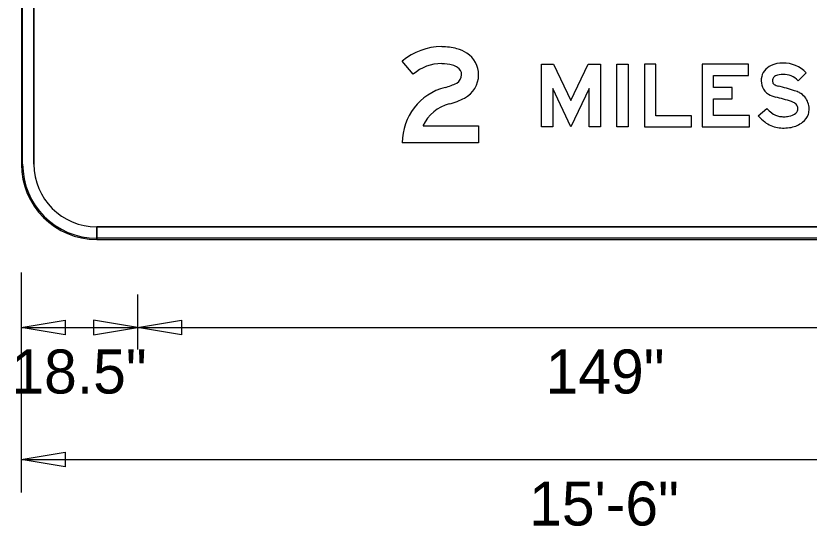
# Model space of a CAD drawing. Extents: x 2149961 to 2150220, y 145114 to 145240.
# Drawn here: x 2149983.36 to 2149993.88, y 145212.96 to 145219.73 of the extents above; entities that cross this region are included whole.
import ezdxf

# ---------------------------------------------------------------- set-up
doc = ezdxf.new("R2010")
doc.units = 0
for name, color, linetype in [('GSBWFILL', 7, 'Continuous'), ('GSCOLORFILL', 7, 'Continuous'), ('GSDIMS', 7, 'Continuous'), ('GSOUTLINE', 7, 'Continuous')]:
    doc.layers.add(name, color=color, linetype=linetype)

msp = doc.modelspace()

# ---------------------------------------------------------------- linework, layer by layer
at = {"layer": 'GSBWFILL'}
for p, q in [((2149983.43, 145232.262), (2149983.43, 145217.762)), ((2149983.596, 145217.762), (2149983.596, 145232.262)), ((2149984.43, 145216.762), (2149984.43, 145216.929)), ((2149997.93, 145216.929), (2149984.431, 145216.929)), ((2149984.431, 145216.929), (2149984.431, 145216.762)), ((2149984.431, 145216.762), (2149997.93, 145216.762))]:
    msp.add_line(p, q, dxfattribs=at)
for points in [[(2149988.628, 145218.954), (2149988.483, 145219.125)], [(2149993.84, 145218.972), (2149993.733, 145218.867)], [(2149993.203, 145218.401), (2149993.317, 145218.499)], [(2149988.758, 145218.27), (2149989.495, 145218.27), (2149989.495, 145218.045), (2149988.483, 145218.045)]]:
    msp.add_lwpolyline(points, dxfattribs=at)
for points in [[(2149990.72, 145218.603), (2149990.95, 145219.087), (2149991.112, 145219.087), (2149991.112, 145218.254), (2149990.962, 145218.254), (2149990.962, 145218.762), (2149990.72, 145218.254), (2149990.478, 145218.762), (2149990.478, 145218.254), (2149990.328, 145218.254), (2149990.328, 145219.087), (2149990.49, 145219.087)], [(2149991.328, 145218.254), (2149991.328, 145219.087), (2149991.478, 145219.087), (2149991.478, 145218.254)], [(2149992.32, 145218.254), (2149992.32, 145218.399), (2149991.845, 145218.399), (2149991.845, 145219.087), (2149991.695, 145219.087), (2149991.695, 145218.254)], [(2149993.087, 145218.404), (2149992.612, 145218.404), (2149992.612, 145218.628), (2149992.858, 145218.628), (2149992.858, 145218.778), (2149992.612, 145218.778), (2149992.612, 145218.937), (2149993.074, 145218.937), (2149993.074, 145219.087), (2149992.462, 145219.087), (2149992.462, 145218.254), (2149993.087, 145218.254)]]:
    msp.add_lwpolyline(points, close=True, dxfattribs=at)
for centre, radius, start, end in [((2149993.532, 145218.703), 0.398, 90, 113.3248), ((2149993.532, 145218.67), 0.431, 44.4342, 90), ((2149993.461, 145218.869), 0.218, 113.3248, 174.1421), ((2149993.481, 145218.867), 0.238, 174.1421, 201.2247), ((2149993.461, 145218.869), 0.0679, 113.3248, 174.1421), ((2149993.481, 145218.867), 0.0882, 174.1421, 201.2247), ((2149993.532, 145218.703), 0.248, 90, 113.3248), ((2149993.532, 145218.67), 0.281, 44.4342, 90), ((2149993.433, 145218.848), 0.186, 201.2247, 240.1812), ((2149993.433, 145218.848), 0.0363, 201.2247, 240.1812), ((2149993.519, 145218.998), 0.209, 240.1812, 256.1067), ((2149992.497, 145214.868), 4.045, 72.8961, 76.1067), ((2149993.519, 145218.998), 0.359, 240.1812, 256.1067), ((2149993.569, 145218.352), 0.4, 63.0108, 72.8961), ((2149993.65, 145218.51), 0.222, 39.5561, 63.0108), ((2149992.497, 145214.868), 3.895, 72.8961, 76.1067), ((2149993.569, 145218.352), 0.25, 63.0108, 72.8961), ((2149993.65, 145218.51), 0.0724, 39.5561, 63.0108), ((2149993.629, 145218.493), 0.0993, 0, 39.5561), ((2149993.629, 145218.493), 0.249, 0, 39.5561), ((2149993.643, 145218.781), 0.43, 220.8202, 232.6492), ((2149993.671, 145218.483), 0.0563, 306.0677, 343.4972), ((2149993.635, 145218.493), 0.0932, 343.4972, 0), ((2149993.635, 145218.493), 0.243, 343.4972, 0), ((2149993.643, 145218.781), 0.58, 220.8202, 232.6492), ((2149993.522, 145218.622), 0.231, 232.6492, 260.7349), ((2149993.547, 145218.777), 0.388, 260.7349, 270), ((2149993.547, 145218.695), 0.306, 270, 281.6446), ((2149993.56, 145218.635), 0.245, 281.6446, 306.0677), ((2149993.671, 145218.483), 0.206, 306.0677, 343.4972), ((2149993.522, 145218.622), 0.381, 232.6492, 260.7349), ((2149993.547, 145218.777), 0.538, 260.7349, 270), ((2149993.547, 145218.695), 0.456, 270, 281.6446), ((2149993.56, 145218.635), 0.395, 281.6446, 306.0677), ((2149984.43, 145217.762), 1, 180, 270), ((2149984.43, 145217.762), 0.833, 180, 270)]:
    msp.add_arc(centre, radius, start, end, dxfattribs=at)
for centre, major_axis, start_param, end_param in [((2149989.005, 145218.511), (0, 0.807), 0, 0.70376), ((2149989.005, 145218.527), (0, 0.79), 6.02311, 6.283185), ((2149989.09, 145218.847), (0, 0.458), 5.706931, 6.02311), ((2149989.153, 145218.945), (0, 0.342), 4.712389, 5.706931), ((2149989.005, 145218.511), (0, 0.582), 0, 0.70376), ((2149989.005, 145218.527), (0, 0.565), 6.02311, 6.283185), ((2149989.09, 145218.847), (0, 0.233), 5.706931, 6.02311), ((2149989.153, 145218.945), (0, 0.117), 4.712389, 5.706931), ((2149989.146, 145218.945), (0, 0.124), 3.626327, 4.712389), ((2149989.146, 145218.945), (0, 0.349), 3.626327, 4.712389), ((2149989.237, 145218.045), (0, 0.755), 0.25053, 1.570796), ((2149988.876, 145219.459), (0, 0.704), 3.392123, 3.626327), ((2149989.237, 145218.045), (0, 0.53), 0.25053, 1.132058), ((2149988.876, 145219.459), (0, 0.929), 3.392123, 3.626327)]:
    msp.add_ellipse(centre, major_axis=major_axis, ratio=0.999997, start_param=start_param, end_param=end_param, dxfattribs=at)
at = {"layer": 'GSCOLORFILL'}
for p, q in [((2149983.43, 145232.262), (2149983.43, 145217.762)), ((2149983.43, 145232.262), (2149983.43, 145217.762)), ((2149983.43, 145232.262), (2149983.43, 145217.762)), ((2149983.446, 145217.762), (2149983.446, 145232.262)), ((2149983.596, 145217.762), (2149983.596, 145232.262)), ((2149984.43, 145216.762), (2149984.43, 145216.929)), ((2149997.93, 145216.929), (2149984.431, 145216.929)), ((2149984.431, 145216.929), (2149984.431, 145216.762)), ((2149984.43, 145216.762), (2149984.43, 145216.779)), ((2149997.93, 145216.779), (2149984.43, 145216.779)), ((2149984.43, 145216.779), (2149984.43, 145216.762)), ((2149984.43, 145216.762), (2149997.93, 145216.762)), ((2149984.43, 145216.762), (2149997.93, 145216.762)), ((2149984.431, 145216.762), (2149997.93, 145216.762))]:
    msp.add_line(p, q, dxfattribs=at)
for points in [[(2149988.628, 145218.954), (2149988.483, 145219.125)], [(2149993.84, 145218.972), (2149993.733, 145218.867)], [(2149993.203, 145218.401), (2149993.317, 145218.499)], [(2149988.758, 145218.27), (2149989.495, 145218.27), (2149989.495, 145218.045), (2149988.483, 145218.045)]]:
    msp.add_lwpolyline(points, dxfattribs=at)
for points in [[(2149990.72, 145218.603), (2149990.95, 145219.087), (2149991.112, 145219.087), (2149991.112, 145218.254), (2149990.962, 145218.254), (2149990.962, 145218.762), (2149990.72, 145218.254), (2149990.478, 145218.762), (2149990.478, 145218.254), (2149990.328, 145218.254), (2149990.328, 145219.087), (2149990.49, 145219.087)], [(2149991.328, 145218.254), (2149991.328, 145219.087), (2149991.478, 145219.087), (2149991.478, 145218.254)], [(2149992.32, 145218.254), (2149992.32, 145218.399), (2149991.845, 145218.399), (2149991.845, 145219.087), (2149991.695, 145219.087), (2149991.695, 145218.254)], [(2149993.087, 145218.404), (2149992.612, 145218.404), (2149992.612, 145218.628), (2149992.858, 145218.628), (2149992.858, 145218.778), (2149992.612, 145218.778), (2149992.612, 145218.937), (2149993.074, 145218.937), (2149993.074, 145219.087), (2149992.462, 145219.087), (2149992.462, 145218.254), (2149993.087, 145218.254)]]:
    msp.add_lwpolyline(points, close=True, dxfattribs=at)
for centre, radius, start, end in [((2149993.532, 145218.703), 0.398, 90, 113.3248), ((2149993.532, 145218.67), 0.431, 44.4342, 90), ((2149993.461, 145218.869), 0.218, 113.3248, 174.1421), ((2149993.481, 145218.867), 0.238, 174.1421, 201.2247), ((2149993.461, 145218.869), 0.0679, 113.3248, 174.1421), ((2149993.481, 145218.867), 0.0882, 174.1421, 201.2247), ((2149993.532, 145218.703), 0.248, 90, 113.3248), ((2149993.532, 145218.67), 0.281, 44.4342, 90), ((2149993.433, 145218.848), 0.186, 201.2247, 240.1812), ((2149993.433, 145218.848), 0.0363, 201.2247, 240.1812), ((2149993.519, 145218.998), 0.209, 240.1812, 256.1067), ((2149992.497, 145214.868), 4.045, 72.8961, 76.1067), ((2149993.519, 145218.998), 0.359, 240.1812, 256.1067), ((2149993.569, 145218.352), 0.4, 63.0108, 72.8961), ((2149993.65, 145218.51), 0.222, 39.5561, 63.0108), ((2149992.497, 145214.868), 3.895, 72.8961, 76.1067), ((2149993.569, 145218.352), 0.25, 63.0108, 72.8961), ((2149993.65, 145218.51), 0.0724, 39.5561, 63.0108), ((2149993.629, 145218.493), 0.0993, 0, 39.5561), ((2149993.629, 145218.493), 0.249, 0, 39.5561), ((2149993.643, 145218.781), 0.43, 220.8202, 232.6492), ((2149993.671, 145218.483), 0.0563, 306.0677, 343.4972), ((2149993.635, 145218.493), 0.0932, 343.4972, 0), ((2149993.635, 145218.493), 0.243, 343.4972, 0), ((2149993.643, 145218.781), 0.58, 220.8202, 232.6492), ((2149993.522, 145218.622), 0.231, 232.6492, 260.7349), ((2149993.547, 145218.777), 0.388, 260.7349, 270), ((2149993.547, 145218.695), 0.306, 270, 281.6446), ((2149993.56, 145218.635), 0.245, 281.6446, 306.0677), ((2149993.671, 145218.483), 0.206, 306.0677, 343.4972), ((2149993.522, 145218.622), 0.381, 232.6492, 260.7349), ((2149993.547, 145218.777), 0.538, 260.7349, 270), ((2149993.547, 145218.695), 0.456, 270, 281.6446), ((2149993.56, 145218.635), 0.395, 281.6446, 306.0677), ((2149984.43, 145217.762), 1, 180, 270), ((2149984.43, 145217.762), 1, 180, 270), ((2149984.43, 145217.762), 1, 180, 270), ((2149984.43, 145217.762), 0.983, 180, 270), ((2149984.43, 145217.762), 0.833, 180, 270)]:
    msp.add_arc(centre, radius, start, end, dxfattribs=at)
for centre, major_axis, start_param, end_param in [((2149989.005, 145218.511), (0, 0.807), 0, 0.70376), ((2149989.005, 145218.527), (0, 0.79), 6.02311, 6.283185), ((2149989.09, 145218.847), (0, 0.458), 5.706931, 6.02311), ((2149989.153, 145218.945), (0, 0.342), 4.712389, 5.706931), ((2149989.005, 145218.511), (0, 0.582), 0, 0.70376), ((2149989.005, 145218.527), (0, 0.565), 6.02311, 6.283185), ((2149989.09, 145218.847), (0, 0.233), 5.706931, 6.02311), ((2149989.153, 145218.945), (0, 0.117), 4.712389, 5.706931), ((2149989.146, 145218.945), (0, 0.124), 3.626327, 4.712389), ((2149989.146, 145218.945), (0, 0.349), 3.626327, 4.712389), ((2149989.237, 145218.045), (0, 0.755), 0.25053, 1.570796), ((2149988.876, 145219.459), (0, 0.704), 3.392123, 3.626327), ((2149989.237, 145218.045), (0, 0.53), 0.25053, 1.132058), ((2149988.876, 145219.459), (0, 0.929), 3.392123, 3.626327)]:
    msp.add_ellipse(centre, major_axis=major_axis, ratio=0.999997, start_param=start_param, end_param=end_param, dxfattribs=at)
at = {"layer": 'GSDIMS'}
for p, q in [((2149983.429, 145216.324), (2149983.429, 145213.408)), ((2149983.429, 145216.033), (2149983.429, 145215.303)), ((2149984.971, 145216.033), (2149984.971, 145215.303)), ((2149984.971, 145216.033), (2149984.971, 145215.303)), ((2149983.429, 145215.595), (2149984.971, 145215.595)), ((2149984.971, 145215.595), (2149997.388, 145215.595)), ((2149983.429, 145214.283), (2149983.429, 145213.553)), ((2149983.429, 145213.845), (2149998.93, 145213.845))]:
    msp.add_line(p, q, dxfattribs=at)
for points in [[(2149983.429, 145215.595), (2149984.013, 145215.692), (2149984.013, 145215.498)], [(2149984.971, 145215.595), (2149984.388, 145215.692), (2149984.388, 145215.498)], [(2149984.971, 145215.595), (2149985.554, 145215.692), (2149985.554, 145215.498)], [(2149983.429, 145213.845), (2149984.013, 145213.942), (2149984.013, 145213.748)]]:
    msp.add_lwpolyline(points, close=True, dxfattribs=at)
at = {"layer": 'GSOUTLINE'}
for p, q in [((2149983.43, 145232.262), (2149983.43, 145217.762)), ((2149983.596, 145232.262), (2149983.596, 145217.762)), ((2149984.43, 145216.929), (2149997.93, 145216.929)), ((2149984.43, 145216.762), (2149997.93, 145216.762))]:
    msp.add_line(p, q, dxfattribs=at)
for points in [[(2149988.628, 145218.954), (2149988.483, 145219.125)], [(2149993.84, 145218.972), (2149993.733, 145218.867)], [(2149993.203, 145218.401), (2149993.317, 145218.499)], [(2149988.758, 145218.27), (2149989.495, 145218.27), (2149989.495, 145218.045), (2149988.483, 145218.045)]]:
    msp.add_lwpolyline(points, dxfattribs=at)
for points in [[(2149990.72, 145218.603), (2149990.95, 145219.087), (2149991.112, 145219.087), (2149991.112, 145218.254), (2149990.962, 145218.254), (2149990.962, 145218.762), (2149990.72, 145218.254), (2149990.478, 145218.762), (2149990.478, 145218.254), (2149990.328, 145218.254), (2149990.328, 145219.087), (2149990.49, 145219.087)], [(2149991.328, 145218.254), (2149991.328, 145219.087), (2149991.478, 145219.087), (2149991.478, 145218.254)], [(2149992.32, 145218.254), (2149992.32, 145218.399), (2149991.845, 145218.399), (2149991.845, 145219.087), (2149991.695, 145219.087), (2149991.695, 145218.254)], [(2149993.087, 145218.404), (2149992.612, 145218.404), (2149992.612, 145218.628), (2149992.858, 145218.628), (2149992.858, 145218.778), (2149992.612, 145218.778), (2149992.612, 145218.937), (2149993.074, 145218.937), (2149993.074, 145219.087), (2149992.462, 145219.087), (2149992.462, 145218.254), (2149993.087, 145218.254)]]:
    msp.add_lwpolyline(points, close=True, dxfattribs=at)
for centre, radius, start, end in [((2149993.532, 145218.703), 0.398, 90, 113.3248), ((2149993.532, 145218.67), 0.431, 44.4342, 90), ((2149993.461, 145218.869), 0.218, 113.3248, 174.1421), ((2149993.481, 145218.867), 0.238, 174.1421, 201.2247), ((2149993.461, 145218.869), 0.0679, 113.3248, 174.1421), ((2149993.481, 145218.867), 0.0882, 174.1421, 201.2247), ((2149993.532, 145218.703), 0.248, 90, 113.3248), ((2149993.532, 145218.67), 0.281, 44.4342, 90), ((2149993.433, 145218.848), 0.186, 201.2247, 240.1812), ((2149993.433, 145218.848), 0.0363, 201.2247, 240.1812), ((2149993.519, 145218.998), 0.209, 240.1812, 256.1067), ((2149992.497, 145214.868), 4.045, 72.8961, 76.1067), ((2149993.519, 145218.998), 0.359, 240.1812, 256.1067), ((2149993.569, 145218.352), 0.4, 63.0108, 72.8961), ((2149993.65, 145218.51), 0.222, 39.5561, 63.0108), ((2149992.497, 145214.868), 3.895, 72.8961, 76.1067), ((2149993.569, 145218.352), 0.25, 63.0108, 72.8961), ((2149993.65, 145218.51), 0.0724, 39.5561, 63.0108), ((2149993.629, 145218.493), 0.0993, 0, 39.5561), ((2149993.629, 145218.493), 0.249, 0, 39.5561), ((2149993.643, 145218.781), 0.43, 220.8202, 232.6492), ((2149993.671, 145218.483), 0.0563, 306.0677, 343.4972), ((2149993.635, 145218.493), 0.0932, 343.4972, 0), ((2149993.635, 145218.493), 0.243, 343.4972, 0), ((2149993.643, 145218.781), 0.58, 220.8202, 232.6492), ((2149993.522, 145218.622), 0.231, 232.6492, 260.7349), ((2149993.547, 145218.777), 0.388, 260.7349, 270), ((2149993.547, 145218.695), 0.306, 270, 281.6446), ((2149993.56, 145218.635), 0.245, 281.6446, 306.0677), ((2149993.671, 145218.483), 0.206, 306.0677, 343.4972), ((2149993.522, 145218.622), 0.381, 232.6492, 260.7349), ((2149993.547, 145218.777), 0.538, 260.7349, 270), ((2149993.547, 145218.695), 0.456, 270, 281.6446), ((2149993.56, 145218.635), 0.395, 281.6446, 306.0677), ((2149984.43, 145217.762), 1, 180, 270), ((2149984.43, 145217.762), 0.833, 180, 270)]:
    msp.add_arc(centre, radius, start, end, dxfattribs=at)
for centre, major_axis, start_param, end_param in [((2149989.005, 145218.511), (0, 0.807), 0, 0.70376), ((2149989.005, 145218.527), (0, 0.79), 6.02311, 6.283185), ((2149989.09, 145218.847), (0, 0.458), 5.706931, 6.02311), ((2149989.153, 145218.945), (0, 0.342), 4.712389, 5.706931), ((2149989.005, 145218.511), (0, 0.582), 0, 0.70376), ((2149989.005, 145218.527), (0, 0.565), 6.02311, 6.283185), ((2149989.09, 145218.847), (0, 0.233), 5.706931, 6.02311), ((2149989.153, 145218.945), (0, 0.117), 4.712389, 5.706931), ((2149989.146, 145218.945), (0, 0.124), 3.626327, 4.712389), ((2149989.146, 145218.945), (0, 0.349), 3.626327, 4.712389), ((2149989.237, 145218.045), (0, 0.755), 0.25053, 1.570796), ((2149988.876, 145219.459), (0, 0.704), 3.392123, 3.626327), ((2149989.237, 145218.045), (0, 0.53), 0.25053, 1.132058), ((2149988.876, 145219.459), (0, 0.929), 3.392123, 3.626327)]:
    msp.add_ellipse(centre, major_axis=major_axis, ratio=0.999997, start_param=start_param, end_param=end_param, dxfattribs=at)

# ---------------------------------------------------------------- texts
at = {"layer": 'GSDIMS'}
for s, p in [('18.5"', (2149983.298, 145214.72)), ('149"', (2149990.383, 145214.72)), ('15\'-6"', (2149990.165, 145212.97))]:
    msp.add_text(s, height=0.5833, dxfattribs=at).set_placement(p)

doc.saveas('drawing.dxf')
